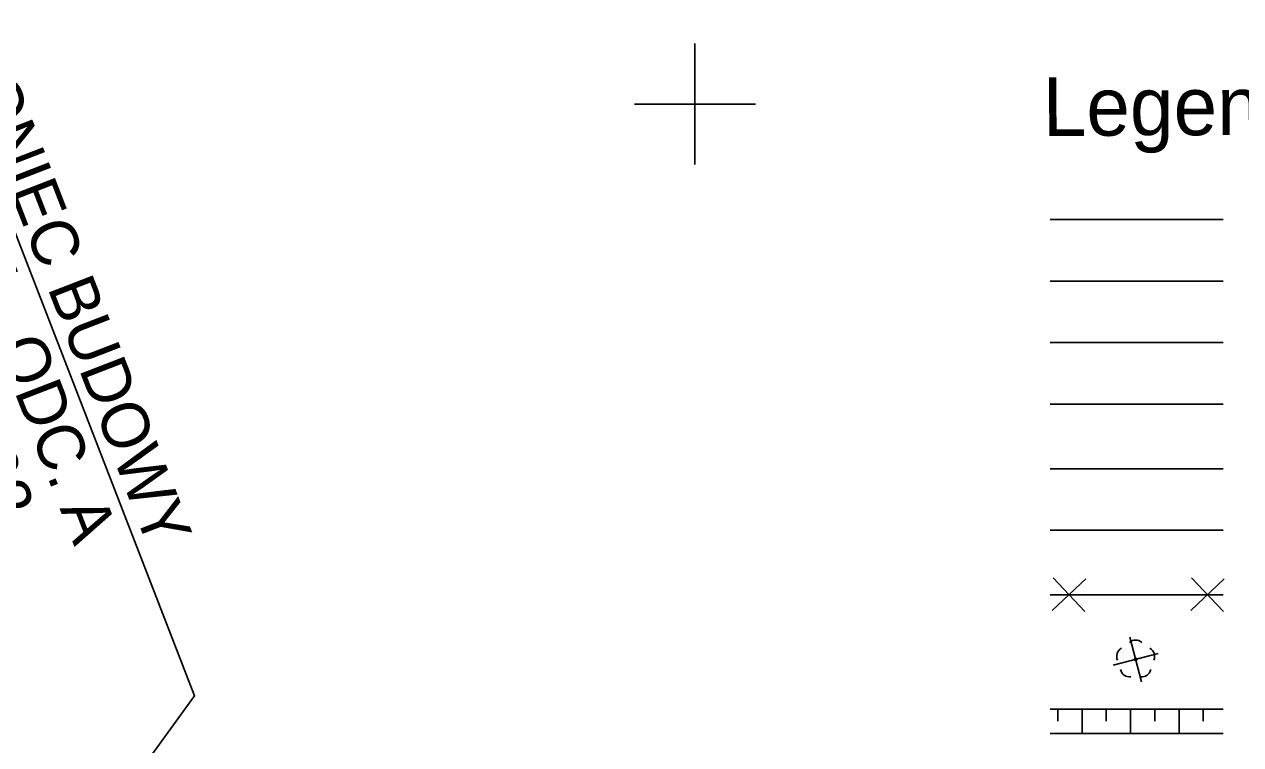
# Model space of a CAD drawing. Extents: x 6512606 to 6513006, y 6022524 to 6022728.
# Drawn here: x 6512872.3 to 6512922.5, y 6022623.6 to 6022653.3 of the extents above; entities that cross this region are included whole.
import ezdxf

# ---------------------------------------------------------------- set-up
doc = ezdxf.new("R2010")
doc.units = 0
for name, color, linetype in [('10', 7, 'Continuous'), ('Default', 7, 'Continuous'), ('drzewo liściaste', 7, 'Continuous'), ('maxp_bariera_ochronna', 7, 'Continuous'), ('maxp_kan_deszczowa', 7, 'Continuous'), ('maxp_likwidacje', 7, 'Continuous'), ('maxp_opisy', 7, 'Continuous'), ('maxp_skarpa', 7, 'Continuous')]:
    doc.layers.add(name, color=color, linetype=linetype)

# ---------------------------------------------------------------- blocks, each defined once
blk = doc.blocks.new('OP021')
at = {"layer": 'Default'}
blk.add_circle((0, 0), 0.5, dxfattribs=at)
for centre, start, end in [((0, 4), 49.272, 130.728), ((-3.8, 1.24), 121.308, 202.548), ((3.8, 1.24), 337.452, 58.692), ((-2.35, -3.24), 193.221, 274.871), ((2.35, -3.24), 265.129, 346.779)]:
    blk.add_arc(centre, 4, start, end, dxfattribs=at)

msp = doc.modelspace()

# ---------------------------------------------------------------- linework, layer by layer
at = {"layer": '10'}
for p, q in [((6512914.661, 6022645.229), (6512921.804, 6022645.229)), ((6512914.661, 6022642.69), (6512921.804, 6022642.69)), ((6512914.661, 6022640.152), (6512921.804, 6022640.152)), ((6512914.661, 6022637.614), (6512921.804, 6022637.614)), ((6512921.804, 6022634.948), (6512914.661, 6022634.948)), ((6512914.745, 6022629.088), (6512916.131, 6022630.401)), ((6512916.095, 6022629.052), (6512914.781, 6022630.437)), ((6512920.461, 6022629.088), (6512921.846, 6022630.401)), ((6512921.811, 6022629.052), (6512920.497, 6022630.437)), ((6512914.661, 6022629.744), (6512921.804, 6022629.744))]:
    msp.add_line(p, q, dxfattribs=at)
at = {"layer": 'Default'}
for p, q in [((6512900, 6022647.5), (6512900, 6022652.5)), ((6512897.5, 6022650), (6512902.5, 6022650))]:
    msp.add_line(p, q, dxfattribs=at)
at = {"layer": 'maxp_bariera_ochronna'}
msp.add_line((6512914.661, 6022632.41), (6512921.804, 6022632.41), dxfattribs=at)
at = {"layer": 'maxp_likwidacje'}
for p, q in [((6512918.426, 6022626.15), (6512917.948, 6022627.998)), ((6512917.263, 6022626.835), (6512919.112, 6022627.313))]:
    msp.add_line(p, q, dxfattribs=at)
at = {"layer": 'maxp_opisy'}
msp.add_lwpolyline([(6512856.121, 6022593.53), (6512879.345, 6022625.572), (6512868.61, 6022653.292)], dxfattribs=at)
at = {"layer": 'maxp_skarpa'}
for p, q in [((6512914.661, 6022625.02), (6512921.804, 6022625.02)), ((6512914.976, 6022625.02), (6512914.976, 6022624.52)), ((6512915.976, 6022625.02), (6512915.976, 6022624.02)), ((6512916.976, 6022625.02), (6512916.976, 6022624.52)), ((6512917.976, 6022625.02), (6512917.976, 6022624.02)), ((6512918.976, 6022625.02), (6512918.976, 6022624.52)), ((6512919.976, 6022625.02), (6512919.976, 6022624.02)), ((6512920.976, 6022625.02), (6512920.976, 6022624.52)), ((6512914.661, 6022624.02), (6512921.804, 6022624.02))]:
    msp.add_line(p, q, dxfattribs=at)

# ---------------------------------------------------------------- block references
at = {"layer": 'drzewo liściaste', "xscale": 0.1, "yscale": 0.10000000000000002}
msp.add_blockref('OP021', (6512918.187, 6022627.074), dxfattribs=at)

# ---------------------------------------------------------------- texts
at = {"layer": 'maxp_kan_deszczowa'}
msp.add_text('Legenda opracowań równoległych:', height=2.42034, rotation=0.2979, dxfattribs=at).set_placement((6512914.357, 6022648.68))
at = {"layer": 'maxp_opisy'}
for s, p in [('KONIEC BUDOWY', (6512869.42, 6022652.352)), ('DROGI - ODC. A', (6512867.279, 6022650.083)), ('km 0+201.92', (6512865.56, 6022646.723))]:
    msp.add_text(s, height=1.936, rotation=291.169, dxfattribs=at).set_placement(p)

doc.saveas('drawing.dxf')
